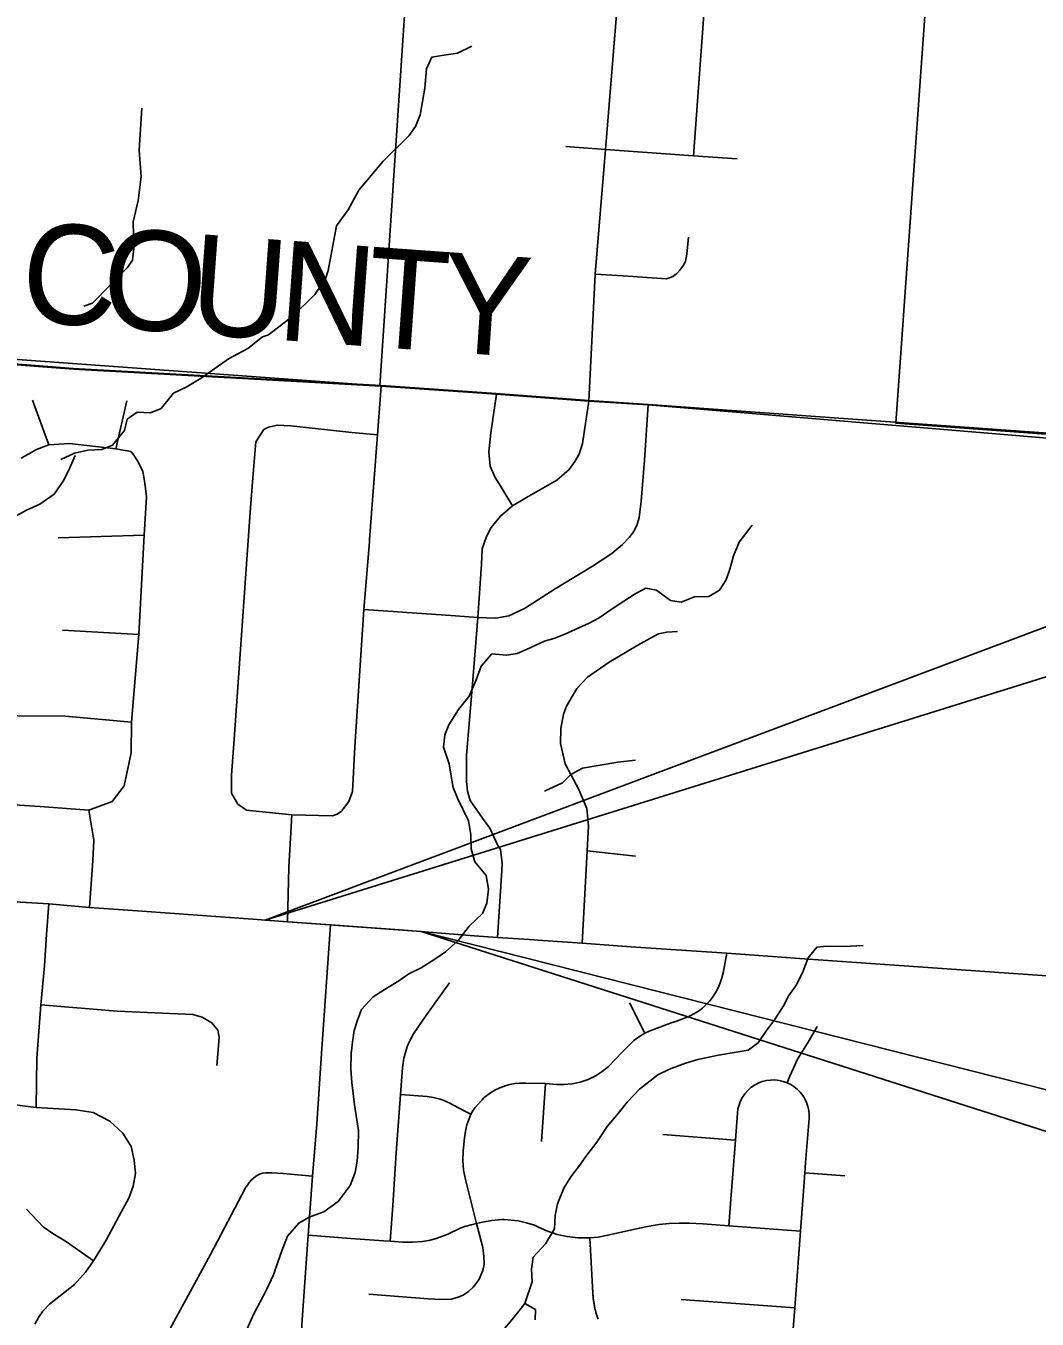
# Model space of a CAD drawing. Extents: x 0 to 34, y 0 to 22.
# Drawn here: x 5.5 to 6.46, y 17.23 to 18.458 of the extents above; entities that cross this region are included whole.
import ezdxf

# ---------------------------------------------------------------- set-up
doc = ezdxf.new("R2010")
doc.units = 0
for name, color, linetype in [('GM_X_Adjacent_County_Text', 7, 'Continuous'), ('GM_X_Corporation', 7, 'Continuous'), ('GM_X_County', 7, 'Continuous'), ('GM_X_County_Road', 7, 'Continuous'), ('GM_X_Minor_Lake', 7, 'Continuous'), ('GM_X_Minor_River', 7, 'Continuous'), ('GM_X_State_Route', 7, 'Continuous'), ('GM_X_Township_Road', 7, 'Continuous'), ('SH_Data', 7, 'Continuous'), ('SH_Text', 7, 'Continuous')]:
    doc.layers.add(name, color=color, linetype=linetype)

msp = doc.modelspace()

# ---------------------------------------------------------------- linework, layer by layer
at = {"layer": 'GM_X_Corporation'}
for points in [[(8.9, 20.9), (4.3071, 20.9), (4.2975, 20.7549), (3.9912, 20.7822), (3.9816, 20.645), (3.9133, 19.6628), (3.9019, 19.4987), (3.8924, 19.3621), (3.8611, 18.9124), (3.8503, 18.7566), (3.8153, 18.2543), (4.1999, 18.2271), (4.3271, 18.2226), (4.5528, 18.2021), (4.7449, 18.1929), (4.9551, 18.1768), (5.5447, 18.1318), (5.8371, 18.1158), (5.9465, 18.1082), (6.0343, 18.1015), (6.0906, 18.0978), (6.5646, 18.0583)], [(3.8501, 18.7572), (3.8151, 18.2549), (4.1997, 18.2276), (4.3269, 18.2232), (4.5421, 18.2046), (4.5794, 18.2013), (4.7454, 18.1936), (4.963, 18.1782), (5.5445, 18.1323), (5.8369, 18.1163), (5.9463, 18.1087), (6.0341, 18.1021), (6.0904, 18.0983), (6.5673, 18.064)], [(3.8501, 18.7572), (3.8151, 18.2549), (4.1997, 18.2276), (4.3269, 18.2232), (4.5421, 18.2046), (4.5794, 18.2013), (4.7454, 18.1936), (4.963, 18.1782), (5.5445, 18.1323), (5.8369, 18.1163), (5.9463, 18.1087), (6.0341, 18.1021), (6.0904, 18.0983), (6.5673, 18.064)], [(6.5646, 18.0583), (6.0906, 18.0978), (6.0343, 18.1015), (5.9465, 18.1082), (5.8371, 18.1158), (5.5447, 18.1318), (4.9551, 18.1768), (4.7449, 18.1929), (4.5528, 18.2021), (4.3271, 18.2226), (4.1999, 18.2271), (3.8153, 18.2543), (2.3155, 18.3567), (2.2478, 17.3472), (2.1768, 16.323), (2.2862, 16.3208), (2.366, 16.3159), (2.934, 16.2765), (3.1745, 16.2606), (3.1026, 15.287), (3.0406, 14.4484), (3.0169, 14.1), (8.9, 14.1)], [(6.5673, 18.064), (6.0904, 18.0983), (6.0341, 18.1021), (5.9463, 18.1087), (5.8369, 18.1163), (5.5445, 18.1323), (4.963, 18.1782), (4.7454, 18.1936), (4.5794, 18.2013), (4.5421, 18.2046), (4.3269, 18.2232), (4.1997, 18.2276), (3.8151, 18.2549), (3.3358, 18.2876)], [(6.5673, 18.064), (6.0904, 18.0983), (6.0341, 18.1021), (5.9463, 18.1087), (5.8369, 18.1163), (5.5445, 18.1323), (4.963, 18.1782), (4.7454, 18.1936), (4.5794, 18.2013), (4.5421, 18.2046), (4.3269, 18.2232), (4.1997, 18.2276), (3.8151, 18.2549), (3.3358, 18.2876)]]:
    msp.add_lwpolyline(points, dxfattribs=at)
for points in [[(5.3836, 19.1504), (5.9022, 19.114), (5.8356, 18.116), (5.3174, 18.1535)], [(6.3967, 19.0805), (6.914, 19.0437), (6.8357, 18.0433), (6.3257, 18.0804)]]:
    msp.add_lwpolyline(points, close=True, dxfattribs=at)
at = {"layer": 'GM_X_County'}
msp.add_lwpolyline([(3.3358, 18.2876), (3.8151, 18.2549), (4.1997, 18.2276), (4.3269, 18.2232), (4.5421, 18.2046), (4.5794, 18.2013), (4.7454, 18.1936), (4.963, 18.1782), (5.5445, 18.1323), (5.8369, 18.1163), (5.9463, 18.1087), (6.0341, 18.1021), (6.0904, 18.0983), (6.5673, 18.064)], dxfattribs=at)
at = {"layer": 'GM_X_County_Road'}
msp.add_lwpolyline([(5.6634, 15.8909), (5.6689, 15.9788), (5.6747, 16.0795), (5.6905, 16.2707), (5.7013, 16.4575), (5.7172, 16.6298), (5.7256, 16.7302), (5.7283, 16.7596), (5.7298, 16.7876), (5.7322, 16.8162), (5.7475, 17.0234), (5.7594, 17.1888), (5.762, 17.2294), (5.7677, 17.3098), (5.7719, 17.366), (5.7758, 17.4155), (5.7802, 17.4822), (5.7888, 17.6044)], dxfattribs=at)
at = {"layer": 'GM_X_Minor_Lake'}
msp.add_lwpolyline([(5.9831, 17.2294), (5.9835, 17.2393), (5.9734, 17.2451), (5.963, 17.2319), (5.9526, 17.2195)], dxfattribs=at)
at = {"layer": 'GM_X_Minor_River'}
for points in [[(5.6661, 18.1234), (5.6921, 18.1416), (5.7103, 18.1514), (5.7243, 18.1624), (5.73, 18.1643), (5.7535, 18.1825), (5.774, 18.2026), (5.7842, 18.2174), (5.7865, 18.2253), (5.7946, 18.2678), (5.8056, 18.283), (5.8158, 18.3016), (5.839, 18.3292), (5.8637, 18.3535), (5.8697, 18.3622), (5.8739, 18.3732), (5.8785, 18.3986), (5.8801, 18.4169), (5.885, 18.4279), (5.8945, 18.4294), (5.9096, 18.4316), (5.9229, 18.4384)], [(5.5547, 18.1917), (5.563, 18.1943), (5.5961, 18.2284), (5.601, 18.2352), (5.6022, 18.2462), (5.6015, 18.2717), (5.6064, 18.2918), (5.6091, 18.3142), (5.6073, 18.3396), (5.6096, 18.3795)], [(5.6661, 18.1234), (5.6517, 18.1148), (5.6399, 18.1089), (5.628, 18.0946), (5.6181, 18.0905), (5.6052, 18.091), (5.5957, 18.0843), (5.5933, 18.0737), (5.5818, 18.0597), (5.5719, 18.0557), (5.5586, 18.055), (5.5457, 18.0521), (5.5328, 18.0462)], [(5.4861, 17.9901), (5.5002, 17.9979), (5.5128, 18.0038), (5.5265, 18.0131), (5.5358, 18.0266), (5.5409, 18.0376), (5.5464, 18.05)], [(5.7095, 17.2205), (5.7161, 17.2353), (5.7222, 17.2466), (5.728, 17.2579), (5.7346, 17.2723), (5.7389, 17.2844), (5.7425, 17.295), (5.7479, 17.3089), (5.7587, 17.3214), (5.7686, 17.327), (5.7826, 17.3321), (5.796, 17.3419), (5.8075, 17.3569), (5.8122, 17.3694), (5.8142, 17.38), (5.8151, 17.3933), (5.8153, 17.4092), (5.8139, 17.4195), (5.8118, 17.4336), (5.809, 17.4548), (5.8083, 17.4674), (5.8085, 17.4822), (5.8098, 17.4932), (5.8114, 17.5042), (5.8145, 17.514), (5.8184, 17.5242), (5.8295, 17.5362), (5.8398, 17.5426), (5.8536, 17.5512), (5.8631, 17.5579), (5.8749, 17.5635), (5.8879, 17.5717), (5.8982, 17.5788), (5.91, 17.5897), (5.9204, 17.6033), (5.9331, 17.6153), (5.9373, 17.6251), (5.939, 17.6384), (5.9368, 17.6513), (5.926, 17.6643), (5.9223, 17.6765), (5.9221, 17.6898), (5.92, 17.7031), (5.9096, 17.7245), (5.9052, 17.7348), (5.903, 17.7473), (5.9016, 17.7572), (5.8961, 17.7732), (5.8974, 17.7846), (5.9013, 17.7944), (5.9105, 17.8088), (5.9205, 17.8216), (5.9271, 17.8371), (5.9318, 17.8499), (5.9422, 17.8616), (5.9562, 17.8603), (5.966, 17.8621), (5.9755, 17.8662), (5.9919, 17.8736), (6.0018, 17.8765), (6.0113, 17.8802), (6.0212, 17.8847), (6.0345, 17.8906), (6.044, 17.8958), (6.0563, 17.9044), (6.0673, 17.9115), (6.078, 17.9186), (6.0883, 17.9238), (6.0985, 17.9222), (6.1117, 17.9122), (6.1219, 17.9106), (6.1344, 17.9158), (6.1481, 17.916), (6.1583, 17.922), (6.1645, 17.9318), (6.168, 17.942), (6.1716, 17.9545), (6.177, 17.9677), (6.1893, 17.9839)], [(5.9734, 17.2451), (5.9804, 17.2655), (5.9798, 17.2777), (5.9814, 17.2891), (5.9929, 17.3018), (6.0014, 17.3158), (6.0023, 17.3287), (6.0043, 17.3397), (6.0105, 17.3544), (6.0171, 17.3654), (6.0252, 17.3759), (6.0321, 17.3857), (6.0417, 17.3981), (6.0517, 17.4132), (6.0621, 17.4253), (6.0705, 17.4362), (6.0824, 17.4486), (6.0996, 17.4621), (6.1106, 17.4673), (6.1258, 17.4732), (6.1376, 17.4765), (6.1574, 17.4808), (6.1722, 17.4833), (6.1855, 17.4855), (6.195, 17.4926), (6.2027, 17.5043), (6.2104, 17.5144), (6.2189, 17.5276), (6.2239, 17.5375), (6.2312, 17.5476), (6.2374, 17.5597), (6.2425, 17.573), (6.2505, 17.5831), (6.26, 17.5842), (6.2706, 17.584), (6.2827, 17.5843), (6.2945, 17.5849)]]:
    msp.add_lwpolyline(points, dxfattribs=at)
at = {"layer": 'GM_X_State_Route'}
for points in [[(4.8671, 17.6692), (4.9115, 17.6662), (4.9281, 17.6651), (5.021, 17.6589), (5.1003, 17.6536), (5.1694, 17.6485), (5.2129, 17.6455), (5.2975, 17.6396), (5.3367, 17.6366), (5.4295, 17.6299), (5.5215, 17.6244), (5.5599, 17.6209), (5.6099, 17.6175), (5.715, 17.6097), (5.748, 17.6073), (5.7888, 17.6044), (5.8589, 17.5993), (5.9254, 17.5939), (5.9473, 17.5925), (5.9774, 17.5906)], [(5.9774, 17.5906), (5.9905, 17.5897), (6.0278, 17.587), (6.0741, 17.5836), (6.1651, 17.5775), (6.2475, 17.5714), (6.528, 17.552)]]:
    msp.add_lwpolyline(points, dxfattribs=at)
at = {"layer": 'GM_X_Township_Road'}
for p, q in [((5.5215, 18.06), (5.506, 18.1023)), ((5.5849, 18.0563), (5.5956, 18.1017)), ((5.5303, 17.9718), (5.6119, 17.9744)), ((5.5343, 17.884), (5.6068, 17.8801)), ((6.0327, 17.6747), (6.0785, 17.6695)), ((6.0874, 17.5017), (6.0727, 17.5303)), ((5.9892, 17.3989), (5.9931, 17.4537)), ((6.1043, 17.4054), (6.1733, 17.4002)), ((6.2393, 17.3692), (6.2771, 17.3663)), ((6.1219, 17.2489), (6.2296, 17.2408))]:
    msp.add_line(p, q, dxfattribs=at)
for points in [[(6.1334, 18.3343), (6.146, 18.5033), (6.1506, 18.5908)], [(6.0343, 18.1015), (6.0402, 18.2219), (6.0499, 18.3404), (6.0608, 18.4722), (6.0615, 18.4764), (6.0619, 18.4794), (6.063, 18.4828), (6.0645, 18.4882), (6.0664, 18.492), (6.069, 18.495), (6.0709, 18.4973), (6.0739, 18.5011), (6.0766, 18.5034), (6.0807, 18.5061), (6.0868, 18.5065), (6.0906, 18.5065), (6.0955, 18.5065), (6.1065, 18.5062), (6.146, 18.5033)], [(6.0124, 18.3432), (6.0499, 18.3404), (6.1334, 18.3343), (6.1749, 18.3313)], [(6.0402, 18.2219), (6.0669, 18.2205), (6.103, 18.218), (6.1076, 18.2176), (6.1106, 18.2184), (6.114, 18.2199), (6.1178, 18.2226), (6.1204, 18.2256), (6.1235, 18.2295), (6.1258, 18.2341), (6.1273, 18.2409), (6.1288, 18.2572)], [(5.7992, 17.7122), (5.8064, 17.7216), (5.8096, 17.7309), (5.812, 17.7733), (5.8206, 17.9037), (5.8258, 17.9678), (5.826, 17.9702), (5.8335, 18.0695), (5.8371, 18.1158)], [(5.9617, 18.0022), (5.9491, 18.0229), (5.9452, 18.0291), (5.9406, 18.0398), (5.9391, 18.0532), (5.9412, 18.0715), (5.9465, 18.1082)], [(5.8206, 17.9037), (5.9075, 17.8976), (5.9289, 17.896), (5.946, 17.8956), (5.9581, 17.8976), (5.9732, 17.9045), (6.0021, 17.9232), (6.0376, 17.9449), (6.056, 17.9567), (6.066, 17.9653), (6.0727, 17.9723), (6.0765, 17.9775), (6.0796, 17.9835), (6.082, 17.9909), (6.0837, 18.0065), (6.0869, 18.0453), (6.0906, 18.0978)], [(5.9473, 17.5925), (5.9515, 17.6559), (5.9519, 17.6631), (5.9503, 17.6759), (5.9479, 17.6798), (5.94, 17.6962), (5.9332, 17.7057), (5.9216, 17.7225), (5.9189, 17.7312), (5.9181, 17.7404), (5.9181, 17.7655), (5.9236, 17.8329), (5.9289, 17.896), (5.9322, 17.9466), (5.933, 17.9613), (5.937, 17.9729), (5.9413, 17.9814), (5.9504, 17.9922), (5.9617, 18.0022), (5.9751, 18.0099), (6.0037, 18.0264), (6.0156, 18.0365), (6.0208, 18.0441), (6.0251, 18.0511), (6.0281, 18.0614), (6.0343, 18.1015)], [(5.7181, 18.0628), (5.7257, 18.0744), (5.7299, 18.0769), (5.7383, 18.0788), (5.7511, 18.0781), (5.8092, 18.0718), (5.8335, 18.0695)], [(5.4952, 18.0473), (5.5096, 18.0556), (5.5215, 18.06), (5.5412, 18.0611), (5.5849, 18.0563), (5.5992, 18.0536), (5.6022, 18.0501), (5.6056, 18.0448), (5.6108, 18.0349), (5.6126, 18.0235), (5.6141, 18.0105), (5.6119, 17.9744), (5.6068, 17.8801), (5.5999, 17.7967)], [(5.7008, 17.7189), (5.6949, 17.7293), (5.6949, 17.7466), (5.6973, 17.7808), (5.7126, 17.996), (5.7152, 18.0286), (5.7181, 18.0628)], [(6.0278, 17.587), (6.0327, 17.6747), (6.0339, 17.6982), (6.0323, 17.7149), (6.0248, 17.7328), (6.0172, 17.7472), (6.0116, 17.7571), (6.0074, 17.7764), (6.0077, 17.7908), (6.01, 17.8043), (6.013, 17.8119), (6.0228, 17.8286), (6.033, 17.8395), (6.0534, 17.8536), (6.0806, 17.8697), (6.092, 17.8763), (6.1004, 17.8805), (6.1081, 17.8822), (6.1182, 17.8828)], [(5.5999, 17.7967), (5.5369, 17.8025), (5.4467, 17.8032)], [(5.3386, 17.7214), (5.353, 17.7243), (5.3665, 17.7252), (5.3841, 17.7239), (5.4294, 17.7217), (5.4685, 17.7196), (5.5132, 17.7167), (5.5383, 17.715), (5.5593, 17.7134), (5.5814, 17.7215), (5.5931, 17.7363), (5.5995, 17.7676), (5.5999, 17.7967)], [(5.9921, 17.7312), (6.0092, 17.7392), (6.0172, 17.7472), (6.028, 17.7531), (6.0618, 17.7587), (6.0785, 17.7607)], [(5.5599, 17.6209), (5.5631, 17.6655), (5.5641, 17.6848), (5.5593, 17.7134)], [(5.7008, 17.7189), (5.709, 17.7133), (5.7522, 17.7087), (5.7909, 17.7079), (5.7952, 17.7095), (5.7992, 17.7122)], [(5.748, 17.6073), (5.7493, 17.6591), (5.7522, 17.7087)], [(5.5094, 17.4312), (5.5101, 17.478), (5.5139, 17.5286), (5.5172, 17.5656), (5.5192, 17.5953), (5.5215, 17.6244)], [(5.9275, 17.321), (5.9169, 17.3626), (5.9151, 17.3716), (5.9145, 17.3809), (5.9149, 17.3901), (5.9161, 17.4024), (5.917, 17.4085), (5.9184, 17.4145), (5.9221, 17.4246), (5.9244, 17.4287), (5.9262, 17.4312), (5.9324, 17.4381), (5.9348, 17.4406), (5.9407, 17.4451), (5.9449, 17.4476), (5.9497, 17.4498), (5.953, 17.4511), (5.9555, 17.452), (5.9592, 17.4529), (5.964, 17.4537), (5.9684, 17.4541), (5.9743, 17.4542), (5.9931, 17.4537), (6.0035, 17.453), (6.0103, 17.4528), (6.0183, 17.4536), (6.026, 17.4552), (6.0335, 17.4578), (6.041, 17.4615), (6.0468, 17.4651), (6.0527, 17.4699), (6.0662, 17.484), (6.0736, 17.4916), (6.077, 17.4948), (6.0822, 17.4986), (6.0874, 17.5017), (6.0913, 17.5035), (6.0941, 17.5046), (6.1134, 17.5116), (6.1169, 17.5128), (6.1182, 17.5133), (6.1251, 17.5157), (6.1296, 17.5176), (6.134, 17.5199), (6.1382, 17.5225), (6.1421, 17.5255), (6.1457, 17.5288), (6.1491, 17.5324), (6.1521, 17.5363), (6.1548, 17.5404), (6.1571, 17.5448), (6.159, 17.5493), (6.1605, 17.554), (6.1617, 17.5588), (6.1651, 17.5774)], [(5.8454, 17.3042), (5.8481, 17.3381), (5.8513, 17.3879), (5.8554, 17.4435), (5.8573, 17.4687), (5.8585, 17.478), (5.862, 17.4899), (5.8677, 17.501), (5.8764, 17.5139), (5.8874, 17.529), (5.9017, 17.5494)], [(5.5139, 17.5286), (5.5863, 17.5224), (5.6583, 17.5194), (5.6669, 17.5169), (5.6762, 17.5115), (5.6819, 17.5044), (5.683, 17.4979), (5.6822, 17.4858), (5.6808, 17.4708)], [(6.2225, 17.4545), (6.2251, 17.4607), (6.2299, 17.472), (6.2317, 17.4758), (6.2338, 17.4795), (6.2432, 17.4948), (6.2511, 17.5078)], [(5.3251, 17.4572), (5.4356, 17.4497), (5.4482, 17.4495), (5.4584, 17.4468), (5.467, 17.4436), (5.476, 17.4382), (5.4839, 17.4348), (5.4941, 17.433), (5.5094, 17.4312), (5.5471, 17.429), (5.5635, 17.4262), (5.5792, 17.418), (5.5918, 17.4066)], [(6.1671, 17.3188), (6.1693, 17.3483), (6.1733, 17.4002), (6.1752, 17.4257), (6.1757, 17.4297), (6.1768, 17.4336), (6.1782, 17.4374), (6.1801, 17.4409), (6.1824, 17.4442), (6.1851, 17.4473), (6.1881, 17.4499), (6.1915, 17.4522), (6.195, 17.4541), (6.1988, 17.4556), (6.2027, 17.4566), (6.2067, 17.4571), (6.2107, 17.4572), (6.2148, 17.4568), (6.2187, 17.4559), (6.2225, 17.4545)], [(6.2373, 17.3431), (6.2393, 17.3692), (6.24, 17.3789), (6.2432, 17.4206), (6.2433, 17.4244), (6.2429, 17.4283), (6.2421, 17.432), (6.2409, 17.4357), (6.2393, 17.4392), (6.2373, 17.4425), (6.2349, 17.4455), (6.2322, 17.4483), (6.2292, 17.4507), (6.226, 17.4528), (6.2225, 17.4545)], [(5.8554, 17.4435), (5.8807, 17.4415), (5.8868, 17.4405), (5.8929, 17.439), (5.8958, 17.438), (5.9015, 17.4354), (5.9153, 17.4281), (5.9221, 17.4246)], [(5.5082, 17.2254), (5.5115, 17.2317), (5.5157, 17.2377), (5.522, 17.2443), (5.5458, 17.2632), (5.5565, 17.275), (5.5637, 17.2854), (5.5758, 17.3051), (5.5881, 17.3283), (5.5973, 17.3451), (5.6016, 17.3565), (5.6036, 17.3683), (5.6025, 17.3812), (5.5995, 17.3941), (5.5918, 17.4066)], [(5.6216, 17.1936), (5.6422, 17.2317), (5.6749, 17.2917), (5.6981, 17.3356), (5.7083, 17.3549), (5.7099, 17.3575), (5.7117, 17.36), (5.7138, 17.3624), (5.7161, 17.3644), (5.7187, 17.3661), (5.7214, 17.3677), (5.7243, 17.3687), (5.7273, 17.3692), (5.7333, 17.3691), (5.7438, 17.3684), (5.7719, 17.366)], [(6.2257, 17.1898), (6.2296, 17.2408), (6.2351, 17.3137), (6.2373, 17.3431)], [(5.5002, 17.3347), (5.5161, 17.3178), (5.5252, 17.3116), (5.5381, 17.3035), (5.5637, 17.2854)], [(5.7677, 17.3098), (5.8083, 17.3066), (5.8391, 17.3045), (5.8454, 17.3042), (5.8575, 17.3034), (5.8668, 17.3034), (5.876, 17.304), (5.8821, 17.305), (5.8881, 17.3065), (5.8997, 17.3107), (5.9121, 17.3164), (5.9163, 17.318), (5.9225, 17.3197), (5.9275, 17.321), (5.9332, 17.3223), (5.9422, 17.3237), (5.9485, 17.3246), (5.9517, 17.3247)], [(5.8254, 17.2539), (5.8816, 17.2496), (5.8941, 17.2488), (5.9033, 17.2493), (5.9092, 17.2507), (5.9148, 17.2531), (5.9199, 17.2565), (5.9244, 17.2606), (5.9282, 17.2654), (5.9299, 17.268), (5.9336, 17.2765), (5.9347, 17.2824), (5.9346, 17.29), (5.9334, 17.2981), (5.9284, 17.3174), (5.9275, 17.321)], [(5.9517, 17.3247), (5.9538, 17.3247), (5.9605, 17.3243), (5.9669, 17.3235), (5.9751, 17.3217), (5.9826, 17.3195), (5.9864, 17.3175), (5.9944, 17.3141), (6.0042, 17.3107), (6.0135, 17.3086), (6.0238, 17.3073), (6.0351, 17.3073), (6.0429, 17.308), (6.0523, 17.3098), (6.0637, 17.3124)], [(6.0637, 17.3124), (6.0821, 17.3167), (6.0915, 17.3186), (6.1009, 17.32), (6.1104, 17.321), (6.1199, 17.3214), (6.1294, 17.3214), (6.1425, 17.3207), (6.1671, 17.3188), (6.2351, 17.3137)], [(6.0351, 17.3073), (6.038, 17.255), (6.0381, 17.2532), (6.0382, 17.2523), (6.0382, 17.2513), (6.0383, 17.2504), (6.0384, 17.2494), (6.0386, 17.2485), (6.0387, 17.2476), (6.0388, 17.2466), (6.039, 17.2457), (6.0391, 17.2448), (6.0393, 17.2438), (6.0395, 17.2429), (6.0396, 17.242), (6.0398, 17.241), (6.04, 17.2401), (6.0403, 17.2392), (6.0405, 17.2383), (6.0407, 17.2373), (6.0409, 17.2364), (6.0412, 17.2355), (6.0415, 17.2346), (6.0417, 17.2337), (6.042, 17.2328), (6.0423, 17.2319), (6.0426, 17.231), (6.0429, 17.2301)]]:
    msp.add_lwpolyline(points, dxfattribs=at)
at = {"layer": 'SH_Data'}
msp.add_line((5.7267, 17.6088), (5.875, 17.598), dxfattribs=at)
at = {"layer": 'SH_Text'}
for points in [[(9.625, 19.0732), (9.625, 18.8232), (5.7267, 17.6088)], [(9.625, 16.6492), (9.625, 16.3992), (5.875, 17.598)]]:
    msp.add_lwpolyline(points, close=True, dxfattribs=at)

# ---------------------------------------------------------------- texts
at = {"layer": 'GM_X_Adjacent_County_Text'}
for s, rotation, p in [('C', 355.8045, (5.4929, 18.1777)), ('O', 355.8059, (5.5698, 18.1721)), ('U', 355.8065, (5.6533, 18.1659)), ('N', 355.8177, (5.7369, 18.1598)), ('T', 355.862, (5.8205, 18.1537)), ('Y', 356.1003, (5.8916, 18.1486))]:
    msp.add_text(s, height=0.0947, rotation=rotation, dxfattribs=at).set_placement(p)

doc.saveas('drawing.dxf')
